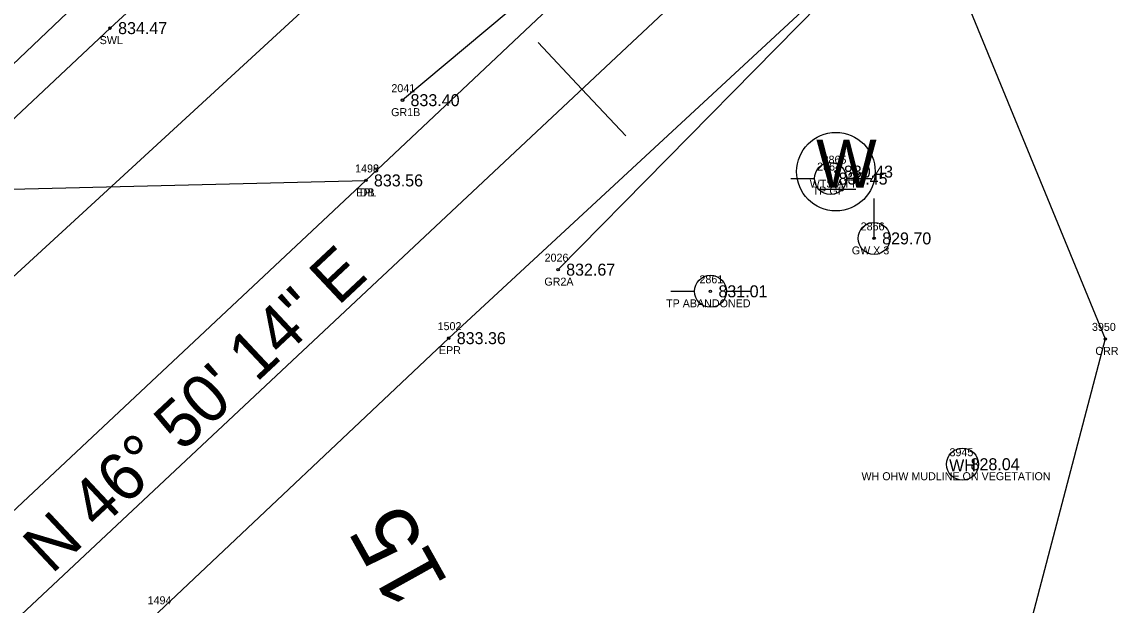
# Model space of a CAD drawing. Extents: x 1622501 to 1626664, y 1117816 to 1121579.
# Drawn here: x 1624283.2 to 1624419.1, y 1119535.3 to 1119608.3 of the extents above; entities that cross this region are included whole.
import ezdxf

# ---------------------------------------------------------------- set-up
doc = ezdxf.new("R2010")
doc.units = 0
for name, color, linetype in [('RD_EX_Conc', 7, 'Continuous'), ('RD_EX_Conc_txCode', 7, 'Continuous'), ('RD_EX_DR_Pipe', 7, 'Continuous'), ('RD_EX_Driveway', 7, 'Continuous'), ('RD_EX_Driveway_txCode', 7, 'Continuous'), ('RD_EX_DV_Prop_txCode', 7, 'Continuous'), ('RD_EX_GuardRail', 7, 'Continuous'), ('RD_EX_GuardRail_txCode', 7, 'Continuous'), ('RD_EX_H2O', 7, 'Continuous'), ('RD_EX_H2O_txCode', 7, 'Continuous'), ('RD_EX_Road', 7, 'Continuous'), ('RD_EX_Road_txCode', 7, 'Continuous'), ('RD_EX_SU_Misc_TxCode', 7, 'Continuous'), ('RD_EX_TX_Conc_ELEV', 7, 'Continuous'), ('RD_EX_TX_Driveway_ELEV', 7, 'Continuous'), ('RD_EX_TX_GuardRail_ELEV', 7, 'Continuous'), ('RD_EX_TX_H2O_ELEV', 7, 'Continuous'), ('RD_EX_TX_Road_ELEV', 7, 'Continuous'), ('RD_EX_TX_UT_ELEV', 7, 'Continuous'), ('RD_EX_UT', 7, 'Continuous'), ('RD_EX_UT_txCode', 7, 'Continuous'), ('RD_HC_Cl', 7, 'Continuous'), ('RD_HC_Data', 7, 'Continuous'), ('RD_HC_Data_Tic', 7, 'Continuous'), ('RD_HC_TX_Sta50', 7, 'Continuous'), ('RD_SMD_Locator', 7, 'Continuous')]:
    doc.layers.add(name, color=color, linetype=linetype)

msp = doc.modelspace()

# ---------------------------------------------------------------- linework, layer by layer
at = {"layer": 'RD_EX_Conc'}
for points in [[(1623883.58, 1119262.31), (1623914.11, 1119291.01), (1623949.14, 1119315.67), (1623997.41, 1119349.7), (1624041.95, 1119381.59), (1624076.33, 1119409.19), (1624117.51, 1119442.93), (1624154.84, 1119473.11), (1624194.15, 1119507.57), (1624227.99, 1119543.89), (1624253.61, 1119575.88), (1624290.62, 1119611.11), (1624311.93, 1119631.19), (1624320.3, 1119640.91)], [(1623887.3, 1119259.13), (1623917.26, 1119287.49), (1623952.1, 1119311.76), (1624000.17, 1119345.78), (1624044.86, 1119377.79), (1624079.21, 1119405.17), (1624120.3, 1119438.84), (1624157.17, 1119468.81), (1624198.23, 1119502.55), (1624231.93, 1119540.84), (1624256.76, 1119572.31), (1624294.22, 1119607.5), (1624315.43, 1119627.07), (1624326.01, 1119634.84)]]:
    msp.add_lwpolyline(points, dxfattribs=at)
at = {"layer": 'RD_EX_DR_Pipe'}
msp.add_lwpolyline([(1623859.42, 1119207.44), (1623928.36, 1119275.93), (1624053.59, 1119378.71), (1624148.05, 1119455.71), (1624257.33, 1119553.63), (1624257.33, 1119553.63), (1624370.57, 1119657.84)], dxfattribs=at)
at = {"layer": 'RD_EX_Driveway'}
msp.add_line((1624272.54, 1119587.13), (1624326.19, 1119588.45), dxfattribs=at)
at = {"layer": 'RD_EX_DV_Prop_txCode'}
msp.add_circle((1624400.75, 1119552.95), 2, dxfattribs=at)
at = {"layer": 'RD_EX_GuardRail'}
for points in [[(1624452.92, 1119710.72), (1624409.47, 1119667.66), (1624375.72, 1119636.16), (1624330.76, 1119598.49)], [(1624350.21, 1119577.29), (1624391.08, 1119618.89), (1624425.11, 1119650.89), (1624471.48, 1119691.28)]]:
    msp.add_lwpolyline(points, dxfattribs=at)
at = {"layer": 'RD_EX_H2O'}
msp.add_lwpolyline([(1624377.74, 1119642.06), (1624397.02, 1119621.14), (1624418.59, 1119568.63), (1624405.37, 1119518.33), (1624408.95, 1119472.53), (1624404.37, 1119367.68), (1624416.34, 1119282.84), (1624404.09, 1119249.08), (1624378.05, 1119258.36), (1624354.29, 1119240.29), (1624341.68, 1119205.27), (1624345.78, 1119173.67)], dxfattribs=at)
at = {"layer": 'RD_EX_Road'}
for points in [[(1623871.53, 1119282.43), (1623877.35, 1119269.36), (1623882.94, 1119261.68), (1623889.32, 1119256.29), (1623900.77, 1119250.58), (1623911.74, 1119248.84), (1623922.61, 1119250.1), (1623930.44, 1119253.06), (1623938.73, 1119260.81), (1623940.66, 1119261.07), (1623977.45, 1119294.81), (1624012.8, 1119327.2), (1624055.34, 1119364.81), (1624091.92, 1119394.37), (1624132.97, 1119426.42), (1624171.16, 1119456.67), (1624210.91, 1119487.9), (1624248.43, 1119517.93), (1624271.21, 1119536.86), (1624326.19, 1119588.45), (1624377.27, 1119636.65)], [(1624155.32, 1119398.39), (1624191.93, 1119432.49), (1624228.15, 1119466.56), (1624264.33, 1119500.12), (1624300.25, 1119534.43), (1624336.54, 1119568.72), (1624392.43, 1119620.52)]]:
    msp.add_lwpolyline(points, dxfattribs=at)
at = {"layer": 'RD_EX_SU_Misc_TxCode'}
msp.add_circle((1624400.75, 1119552.95), 0.005, dxfattribs=at)
at = {"layer": 'RD_EX_UT'}
for p, q in [((1624379.31, 1119588.7), (1624382.24, 1119588.7)), ((1624386.24, 1119588.7), (1624389.31, 1119588.7)), ((1624382.79, 1119587.35), (1624387.42, 1119587.35)), ((1624389.7, 1119581.2), (1624389.7, 1119586.2)), ((1624364.31, 1119574.6), (1624367.24, 1119574.6)), ((1624371.24, 1119574.6), (1624374.31, 1119574.6))]:
    msp.add_line(p, q, dxfattribs=at)
for centre, radius in [((1624384.92, 1119589.55), 4.91), ((1624384.24, 1119588.68), 2), ((1624389.7, 1119581.2), 2), ((1624369.24, 1119574.58), 2)]:
    msp.add_circle(centre, radius, dxfattribs=at)
at = {"layer": 'RD_HC_Cl'}
msp.add_line((1623937.25, 1119209.79), (1624678.65, 1119905.11), dxfattribs=at)
at = {"layer": 'RD_HC_Data_Tic'}
for q in [(1624347.7, 1119605.7), (1624358.65, 1119594.03)]:
    msp.add_line((1624353.17, 1119599.86), q, dxfattribs=at)
at = {"layer": 'RD_SMD_Locator'}
for centre in [(1624294.22, 1119607.5), (1624330.76, 1119598.49), (1624326.19, 1119588.45), (1624326.19, 1119588.45), (1624384.24, 1119588.68), (1624384.92, 1119589.55), (1624389.7, 1119581.2), (1624350.21, 1119577.29), (1624369.24, 1119574.58), (1624336.54, 1119568.72), (1624418.59, 1119568.63)]:
    msp.add_circle(centre, 0.15, dxfattribs=at)

# ---------------------------------------------------------------- texts
at = {"layer": 'RD_EX_Conc_txCode'}
msp.add_text('SWL', height=1, dxfattribs=at).set_placement((1624292.92, 1119605.5))
at = {"layer": 'RD_EX_Driveway_txCode'}
for s, p in [('1498', (1624324.84, 1119589.45)), ('DB', (1624325.41, 1119586.45))]:
    msp.add_text(s, height=1, dxfattribs=at).set_placement(p)
at = {"layer": 'RD_EX_DV_Prop_txCode'}
msp.add_text('WH', height=1.5, dxfattribs=at).set_placement((1624399.07, 1119552.07))
at = {"layer": 'RD_EX_GuardRail_txCode'}
for s, p in [('2041', (1624329.37, 1119599.49)), ('GR1B', (1624329.34, 1119596.49)), ('2026', (1624348.52, 1119578.29)), ('GR2A', (1624348.49, 1119575.29))]:
    msp.add_text(s, height=1, dxfattribs=at).set_placement(p)
at = {"layer": 'RD_EX_H2O_txCode'}
for s, p in [('3950', (1624416.92, 1119569.63)), ('CRR', (1624417.34, 1119566.63)), ('3945', (1624399.12, 1119553.95)), ('WH OHW MUDLINE ON VEGETATION', (1624388.12, 1119550.95))]:
    msp.add_text(s, height=1, dxfattribs=at).set_placement(p)
at = {"layer": 'RD_EX_Road_txCode'}
for s, p in [('1499', (1624324.84, 1119589.45)), ('EPL', (1624324.98, 1119586.45)), ('1502', (1624335.15, 1119569.72)), ('EPR', (1624335.31, 1119566.72)), ('1494', (1624298.91, 1119535.43))]:
    msp.add_text(s, height=1, dxfattribs=at).set_placement(p)
at = {"layer": 'RD_EX_TX_Conc_ELEV'}
msp.add_text('834.47', height=1.5, dxfattribs=at).set_placement((1624295.22, 1119606.75))
at = {"layer": 'RD_EX_TX_Driveway_ELEV'}
msp.add_text('833.56', height=1.5, dxfattribs=at).set_placement((1624327.19, 1119587.7))
at = {"layer": 'RD_EX_TX_GuardRail_ELEV'}
for s, p in [('833.40', (1624331.76, 1119597.74)), ('832.67', (1624351.21, 1119576.54))]:
    msp.add_text(s, height=1.5, dxfattribs=at).set_placement(p)
at = {"layer": 'RD_EX_TX_H2O_ELEV'}
msp.add_text('828.04', height=1.5, dxfattribs=at).set_placement((1624401.75, 1119552.2))
at = {"layer": 'RD_EX_TX_Road_ELEV'}
for s, p in [('833.56', (1624327.19, 1119587.7)), ('833.36', (1624337.54, 1119567.97))]:
    msp.add_text(s, height=1.5, dxfattribs=at).set_placement(p)
at = {"layer": 'RD_EX_TX_UT_ELEV'}
for s, p in [('830.43', (1624385.92, 1119588.8)), ('830.45', (1624385.24, 1119587.93)), ('829.70', (1624390.7, 1119580.45)), ('831.01', (1624370.24, 1119573.83))]:
    msp.add_text(s, height=1.5, dxfattribs=at).set_placement(p)
at = {"layer": 'RD_EX_UT'}
msp.add_text('W', height=6, dxfattribs=at).set_placement((1624382.45, 1119587.55))
at = {"layer": 'RD_EX_UT_txCode'}
for s, p in [('2865', (1624383.26, 1119590.55)), ('2864', (1624382.58, 1119589.68)), ('WTS ATT', (1624381.65, 1119587.55)), ('TP GP', (1624382.02, 1119586.68)), ('2866', (1624388.02, 1119582.2)), ('GW X 3', (1624386.91, 1119579.2)), ('2861', (1624367.87, 1119575.58)), ('TP ABANDONED', (1624363.7, 1119572.58))]:
    msp.add_text(s, height=1, dxfattribs=at).set_placement(p)
at = {"layer": 'RD_HC_Data'}
for s, rotation, p in [('N 29%%d 08\' 00" W', 299.1334, (1624406.3, 1119636.92)), ('N 46%%d 50\' 14" E', 43.1627, (1624286.92, 1119539.1))]:
    msp.add_text(s, height=6, rotation=rotation, dxfattribs=at).set_placement(p)
at = {"layer": 'RD_HC_TX_Sta50'}
msp.add_text('15', height=8, rotation=119.1334, dxfattribs=at).set_placement((1624336.59, 1119538.1))

doc.saveas('drawing.dxf')
